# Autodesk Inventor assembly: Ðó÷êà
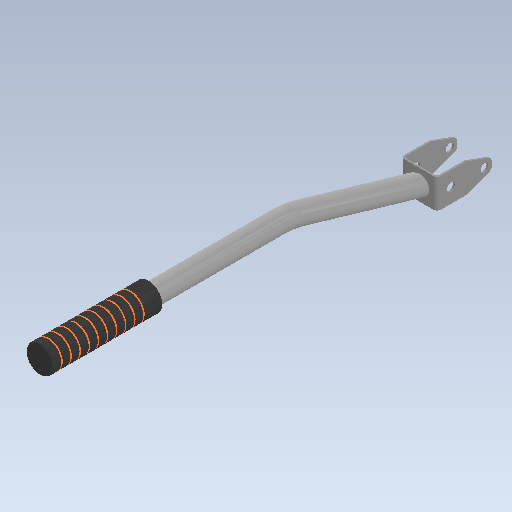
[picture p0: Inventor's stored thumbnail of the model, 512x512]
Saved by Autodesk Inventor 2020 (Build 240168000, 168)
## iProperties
Created: 1900-01
Part Number: Ðó÷êà
Document SubType Name: Assembly
Designer: bruno
Author: bruno
Revision Number: ANYUNSPECIFIED
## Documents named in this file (4)
- C:\Users\bruno\Documents\1-Cours-2022-23\1SI\2. Cinématique\Hoverboard\Inventor-Hoverboard\Ðó÷êà.iam
- C:\Users\bruno\Documents\1-Cours-2022-23\1SI\2. Cinématique\Hoverboard\Inventor-Hoverboard\Òðóáà ðó÷êè.ipt
- C:\Users\bruno\Documents\1-Cours-2022-23\1SI\2. Cinématique\Hoverboard\Inventor-Hoverboard\Âèëêà ðó÷êè.ipt
- C:\Users\bruno\Documents\1-Cours-2022-23\1SI\2. Cinématique\Hoverboard\Inventor-Hoverboard\HANDLE GRIP_1.ipt
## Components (3 placed, 3 different names)
1. 25
2. 26
3. 27
